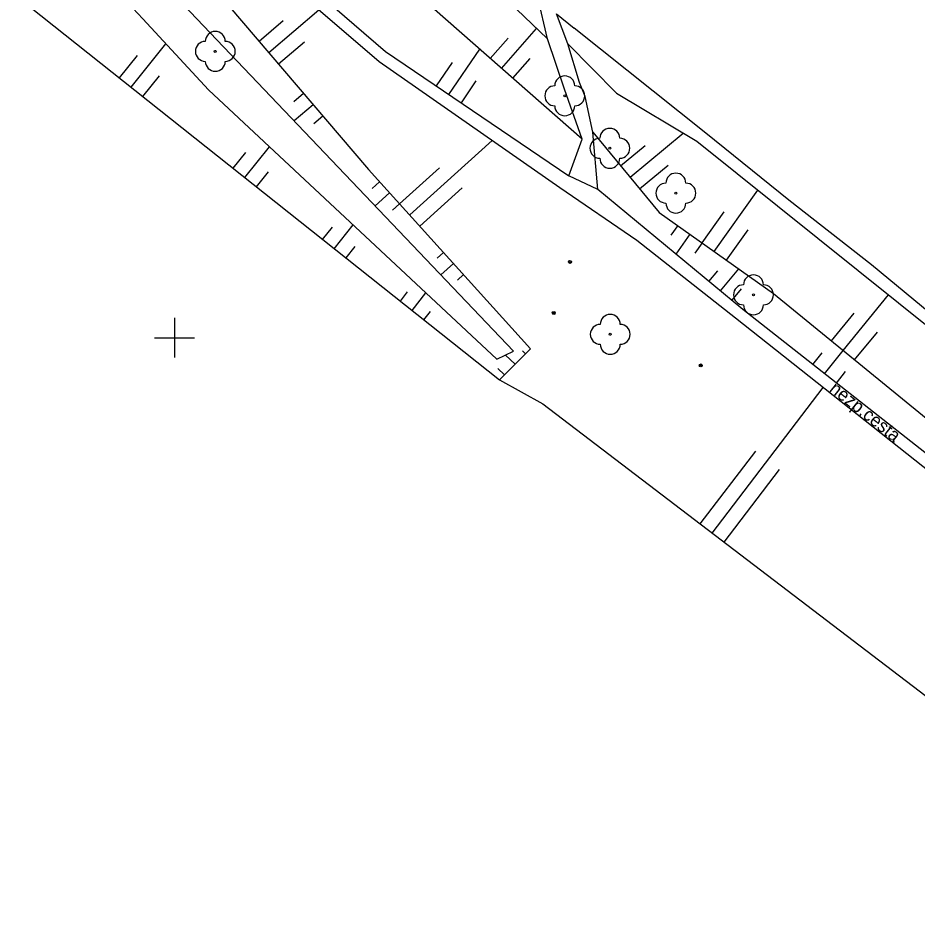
# Model space of a CAD drawing. Extents: x -639440 to -639026, y -1138850 to -1138262.
# Drawn here: x -639207.84 to -639162.72, y -1138728.9 to -1138683.97 of the extents above; entities that cross this region are included whole.
import ezdxf

# ---------------------------------------------------------------- set-up
doc = ezdxf.new("R2010")
doc.units = 0
for name, color, linetype in [('Vrstva 11', 7, 'Continuous'), ('Vrstva 14', 7, 'Continuous'), ('Vrstva 15', 7, 'Continuous'), ('Vrstva 20', 7, 'Continuous'), ('Vrstva 22', 7, 'Continuous'), ('Vrstva 40', 7, 'Continuous'), ('Vrstva 61', 7, 'Continuous'), ('Vrstva 7', 7, 'Continuous'), ('Vrstva 8', 7, 'Continuous')]:
    doc.layers.add(name, color=color, linetype=linetype)

msp = doc.modelspace()

# ---------------------------------------------------------------- linework, layer by layer
at = {"layer": 'Vrstva 11'}
for p, q in [((-639194.57, -1138681.19), (-639189.41, -1138685.64)), ((-639189.73, -1138686.16), (-639194.97, -1138681.67)), ((-639181.3, -1138685.01), (-639181.93, -1138682.29)), ((-639180.28, -1138685.26), (-639180.84, -1138683.76)), ((-639180.44, -1138687.53), (-639181.3, -1138685.01)), ((-639189.41, -1138685.64), (-639180.22, -1138691.88)), ((-639179.69, -1138687.2), (-639180.28, -1138685.26)), ((-639180.68, -1138692.49), (-639189.73, -1138686.16)), ((-639179.41, -1138687.91), (-639179.69, -1138687.2)), ((-639179.56, -1138690.05), (-639180.44, -1138687.53)), ((-639179.03, -1138689.7), (-639179.41, -1138687.91)), ((-639178.78, -1138692.56), (-639179.03, -1138689.7)), ((-639180.22, -1138691.88), (-639179.56, -1138690.05)), ((-639178.78, -1138692.56), (-639180.22, -1138691.88)), ((-639176.81, -1138695.12), (-639180.68, -1138692.49)), ((-639171.51, -1138698.58), (-639178.78, -1138692.56)), ((-639171.87, -1138699.02), (-639176.81, -1138695.12)), ((-639159.35, -1138708.14), (-639171.51, -1138698.58)), ((-639159.73, -1138708.64), (-639171.87, -1138699.02))]:
    msp.add_line(p, q, dxfattribs=at)
at = {"layer": 'Vrstva 14'}
for p, q in [((-639179.56, -1138690.05), (-639192.33, -1138678.81)), ((-639206.21, -1138679.03), (-639201.59, -1138684.01)), ((-639183, -1138700.67), (-639202.41, -1138680.28)), ((-639207.84, -1138682.93), (-639183.7, -1138702.12)), ((-639197.32, -1138683.3), (-639190.27, -1138691.56)), ((-639181.3, -1138685.01), (-639182.85, -1138683.52)), ((-639201.59, -1138684.01), (-639198.29, -1138687.57)), ((-639180.28, -1138685.26), (-639177.83, -1138687.74)), ((-639198.29, -1138687.57), (-639183.83, -1138701.08)), ((-639177.83, -1138687.74), (-639173.81, -1138690.15)), ((-639179.03, -1138689.7), (-639175.69, -1138693.72)), ((-639173.81, -1138690.15), (-639160.11, -1138701.14)), ((-639190.27, -1138691.56), (-639182.15, -1138700.55)), ((-639175.69, -1138693.72), (-639169.97, -1138697.78)), ((-639169.97, -1138697.78), (-639160.55, -1138705.48)), ((-639182.15, -1138700.55), (-639183.7, -1138702.12)), ((-639183.83, -1138701.08), (-639183, -1138700.67)), ((-639183.7, -1138702.12), (-639181.53, -1138703.32)), ((-639181.53, -1138703.32), (-639147.99, -1138728.9))]:
    msp.add_line(p, q, dxfattribs=at)
at = {"layer": 'Vrstva 15'}
for p, q in [((-639195.27, -1138685.701), (-639192.763, -1138683.561)), ((-639195.757, -1138685.131), (-639194.548, -1138684.099)), ((-639183.604, -1138686.491), (-639181.842, -1138684.489)), ((-639194.784, -1138686.272), (-639193.485, -1138685.163)), ((-639184.167, -1138685.995), (-639183.275, -1138684.982)), ((-639202.164, -1138687.442), (-639200.43, -1138685.261)), ((-639186.234, -1138687.797), (-639184.695, -1138685.53)), ((-639202.751, -1138686.975), (-639201.849, -1138685.84)), ((-639183.041, -1138686.986), (-639182.171, -1138685.998)), ((-639186.854, -1138687.375), (-639186.058, -1138686.203)), ((-639201.577, -1138687.909), (-639200.746, -1138686.863)), ((-639185.613, -1138688.218), (-639184.87, -1138687.124)), ((-639193.525, -1138687.746), (-639194.016, -1138688.164)), ((-639193.039, -1138688.316), (-639193.988, -1138689.127)), ((-639192.552, -1138688.887), (-639193.011, -1138689.279)), ((-639177.157, -1138691.955), (-639174.492, -1138689.741)), ((-639188.205, -1138693.846), (-639184.074, -1138690.116)), ((-639196.466, -1138691.972), (-639195.235, -1138690.424)), ((-639177.636, -1138691.378), (-639176.405, -1138690.355)), ((-639197.053, -1138691.505), (-639196.419, -1138690.708)), ((-639188.708, -1138693.29), (-639186.706, -1138691.482)), ((-639176.677, -1138692.532), (-639175.244, -1138691.341)), ((-639195.879, -1138692.438), (-639195.282, -1138691.688)), ((-639189.714, -1138692.176), (-639190.083, -1138692.509)), ((-639189.211, -1138692.733), (-639189.934, -1138693.386)), ((-639187.702, -1138694.403), (-639185.573, -1138692.48)), ((-639172.933, -1138695.677), (-639170.752, -1138692.603)), ((-639188.708, -1138693.289), (-639189.063, -1138693.609)), ((-639173.545, -1138695.243), (-639172.441, -1138693.688)), ((-639192.57, -1138695.069), (-639192.079, -1138694.451)), ((-639191.983, -1138695.536), (-639191.037, -1138694.346)), ((-639174.768, -1138694.374), (-639175.105, -1138694.849)), ((-639172.322, -1138696.111), (-639171.244, -1138694.592)), ((-639174.156, -1138694.808), (-639174.863, -1138695.804)), ((-639191.396, -1138696.002), (-639190.942, -1138695.431)), ((-639173.545, -1138695.243), (-639173.914, -1138695.763)), ((-639186.512, -1138695.72), (-639186.835, -1138696.011)), ((-639186.01, -1138696.277), (-639186.64, -1138696.846)), ((-639185.507, -1138696.833), (-639185.815, -1138697.111)), ((-639173.205, -1138697.176), (-639172.764, -1138696.643)), ((-639172.628, -1138697.655), (-639171.709, -1138696.545)), ((-639188.673, -1138698.167), (-639188.306, -1138697.704)), ((-639188.086, -1138698.633), (-639187.388, -1138697.755)), ((-639172.05, -1138698.133), (-639171.573, -1138697.557)), ((-639166.479, -1138700.633), (-639164.207, -1138697.854)), ((-639187.499, -1138699.1), (-639187.169, -1138698.685)), ((-639167.06, -1138700.159), (-639165.926, -1138698.771)), ((-639165.899, -1138701.108), (-639164.76, -1138699.715)), ((-639182.924, -1138701.334), (-639183.398, -1138700.867)), ((-639182.397, -1138700.8), (-639182.542, -1138700.658)), ((-639167.993, -1138701.345), (-639167.526, -1138700.752)), ((-639167.403, -1138701.809), (-639166.479, -1138700.633)), ((-639183.451, -1138701.868), (-639183.78, -1138701.543)), ((-639166.814, -1138702.272), (-639166.356, -1138701.69)), ((-639173.04, -1138709.795), (-639167.477, -1138702.501)), ((-639173.637, -1138709.34), (-639170.851, -1138705.687)), ((-639172.444, -1138710.25), (-639169.667, -1138706.608))]:
    msp.add_line(p, q, dxfattribs=at)
at = {"layer": 'Vrstva 20'}
for centre, radius in [((-639180.17, -1138696.2), 0.075), ((-639180.17, -1138696.2), 0.0204), ((-639180.98, -1138698.76), 0.075), ((-639180.98, -1138698.76), 0.0204), ((-639173.61, -1138701.39), 0.075), ((-639173.61, -1138701.39), 0.0204)]:
    msp.add_circle(centre, radius, dxfattribs=at)
at = {"layer": 'Vrstva 22'}
for centre in [(-639197.95, -1138685.64), (-639180.43, -1138687.87), (-639178.17, -1138690.5), (-639174.86, -1138692.75), (-639170.97, -1138697.85), (-639178.15, -1138699.83)]:
    msp.add_circle(centre, 0.05, dxfattribs=at)
for centre, start, end in [((-639197.95, -1138685.14), 0, 180), ((-639198.45, -1138685.64), 90, 270), ((-639197.45, -1138685.64), 270, 90), ((-639197.95, -1138686.14), 180, 0), ((-639180.43, -1138687.37), 0, 180), ((-639180.93, -1138687.87), 90, 270), ((-639179.93, -1138687.87), 270, 90), ((-639180.43, -1138688.37), 180, 0), ((-639178.17, -1138690), 0, 180), ((-639178.67, -1138690.5), 90, 270), ((-639177.67, -1138690.5), 270, 90), ((-639178.17, -1138691), 180, 0), ((-639174.86, -1138692.25), 0, 180), ((-639175.36, -1138692.75), 90, 270), ((-639174.36, -1138692.75), 270, 90), ((-639174.86, -1138693.25), 180, 0), ((-639170.97, -1138697.35), 0, 180), ((-639171.47, -1138697.85), 90, 270), ((-639170.47, -1138697.85), 270, 90), ((-639170.97, -1138698.35), 180, 0), ((-639178.15, -1138699.33), 0, 180), ((-639178.65, -1138699.83), 90, 270), ((-639177.65, -1138699.83), 270, 90), ((-639178.15, -1138700.33), 180, 0)]:
    msp.add_arc(centre, 0.5, start, end, dxfattribs=at)
at = {"layer": 'Vrstva 61'}
for p, q in [((-639200, -1138699), (-639200, -1138701)), ((-639201, -1138700), (-639199, -1138700))]:
    msp.add_line(p, q, dxfattribs=at)
at = {"layer": 'Vrstva 7'}
for p, q in [((-639173.36, -1138689.75), (-639179.96, -1138684.47)), ((-639169.19, -1138693.1), (-639173.36, -1138689.75)), ((-639165.06, -1138696.35), (-639169.19, -1138693.1)), ((-639161.06, -1138699.65), (-639165.06, -1138696.35))]:
    msp.add_line(p, q, dxfattribs=at)
at = {"layer": 'Vrstva 8'}
msp.add_line((-639180.84, -1138683.76), (-639179.96, -1138684.47), dxfattribs=at)

# ---------------------------------------------------------------- texts
at = {"layer": 'Vrstva 40'}
msp.add_text('nezp.cesta', height=0.65, rotation=321.6059, dxfattribs=at).set_placement((-639167.209, -1138702.654))

doc.saveas('drawing.dxf')
